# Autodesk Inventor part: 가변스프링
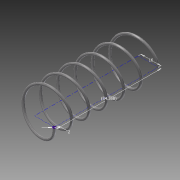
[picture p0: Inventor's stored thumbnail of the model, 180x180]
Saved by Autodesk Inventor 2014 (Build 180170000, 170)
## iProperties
Created: 2016-11
Part Number: 가변스프링
Material: 강철, 탄소
Document SubType Name: Modeling
Designer: NET
Density: 7.87 g/cm^3
Appearance: 반연마
Author: NET
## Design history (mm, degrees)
sketch "스케치1"
  geometry: L1 (0, 0)-(16, 0); L2 (16, 0)-(16, 84.368); L3 (16, 84.368)-(0, 84.368); L4 (0, 84.368)-(0, 0); C1 r 1 at (16, 0)
  constraints: 8 end point, 2 parallel, 1 centre point, 1 coincident, 1 horizontal, 1 perpendicular
  dimensions: "d0" = 16 distance of L3.end L2.end; "d1" = 84.36759 distance of L2.end L1.end (derived); "d2" = 2 diameter of C1
feature "코일1" pitch "d3" = 10; turns "d5" = 6; dims "d4" = 84.36759 (= d1), "d6" = 0, angle "d7" = 90 deg, angle "d8" = 90 deg, "d9" = 0, "d10" = 0
node "작업 평면2"
node "작업 평면3"
sketch "스케치4"
  geometry: L1 (15, 0)-(17, 0) reference; 1 further point
  constraints: 1 horizontal alignment
extrude "돌출3" cut sketch "스케치4" distance "d16" = 10; taper "d17" = 0 deg
sketch "스케치5"
  geometry: L1 (17, 0)-(15, 0) reference; 1 further point
  constraints: 1 horizontal alignment
extrude "돌출4" cut sketch "스케치5" distance "d18" = 10; taper "d19" = 0 deg
node "솔리드1"
node "절단 모서리 투영3"
node "절단 모서리 투영4"
